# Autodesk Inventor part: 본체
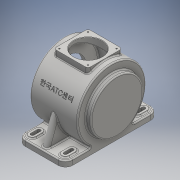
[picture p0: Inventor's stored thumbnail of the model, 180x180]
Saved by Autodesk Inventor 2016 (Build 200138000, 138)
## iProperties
Created: 2015-06
Part Number: 본체
Material: Generic
Document SubType Name: Modeling
Designer: Administrator
Density: 1 g/cm^3
Appearance: Default
Author: Administrator
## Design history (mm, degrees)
sketch "스케치1"
  geometry: C1 r 85 at (0, 0); 1 further point
  constraints: 1 centre point, 1 coincident
  dimensions: "d0" = 170 diameter of C1
extrude "돌출1" new body sketch "스케치1" stored distance "d1" = 118; taper "d3" = 0 deg; dims "d2" = 51, "d4" = 0
sketch "스케치3"
  geometry: C1 r 65 at (0, 0); 1 further point
  constraints: 1 centre point, 1 coincident
  dimensions: "d5" = 130 diameter of C1
extrude "돌출2" join sketch "스케치3" distance "d6" = 13; taper "d7" = 0 deg
sketch "스케치4"
  geometry: C1 r 65 at (0, 0); 1 further point
  constraints: 1 centre point, 1 coincident
  dimensions: "d8" = 130 diameter of C1
extrude "돌출3" join sketch "스케치4" distance "d9" = 3; taper "d10" = 0 deg
sketch "스케치7"
  geometry: L1 (71, -115)-(85, -115); L2 (85, -115)-(85, 115); L3 (85, 115)-(71, 115); L4 (71, 115)-(71, -115); 2 further points
  constraints: 8 end point, 2 parallel, 1 horizontal, 1 horizontal alignment, 1 midpoint, 1 perpendicular
  dimensions: "d16" = 14 distance of L2.end L3.end; "d17" = 230 distance of L3.end L1.start; "d18" = 85 distance from line of L2 point (0, 0)
extrude "돌출5" join sketch "스케치7" stored distance "d19" = 3; taper "d20" = 0 deg
sketch "스케치8"
  geometry: L1 (-62, 65)-(-62, -65) reference; L2 (-59, -85)-(59, -85) reference; L3 (-59, 85)-(59, 85) reference; L4 (72, 0)-(-62, 0); L5 (-51, 47.5)-(-51, 77); L6 (-51, 77)-(51, 77); L7 (51, 77)-(51, 31); L8 (51, 31)-(47.042, 29.154); L9 (47.042, 29.154)-(47.042, 23.5); L10 (47.042, 23.5)-(61.042, 23.5); L11 (61.042, 23.5)-(61.042, 15); L12 (61.042, 15)-(64.042, 15); L13 (72, -65)-(72, 65) reference; L14 (64.042, 15)-(64.042, 0); L15 (-51, 47.5)-(-62, 47.5); L16 (-62, 47.5)-(-62, 0); 1 further point
  constraints: 24 end point, 5 perpendicular, 2 midpoint, 2 point on line, 1 parallel, 1 vertical
  dimensions: "d21" = 3 distance of L11.end L12.end; "d23" = 30 diameter of L12 L4; "d24" = 14 distance of L9.end L10.end; "d25" = 47 diameter of L10 L4; "d26" = 115 deg angle of L7 L8; "d27" = 102 distance between parallel lines of L5 L7; "d28" = 62 diameter of L7.end L4; "d29" = 154 diameter of L6 L4; "d30" = 95 diameter of L15 L4; "d31" = 11 distance of L5.start L15.end; "d32" = 3.9582 distance from line of L7 L8.end
revolve "회전1" sketch "스케치8" stored, may be unused: angle "d33" = 90 deg
sketch "스케치9"
  geometry: L1 (-115, -71)-(-46.733, -71) reference; L2 (115, -85)-(-115, -85) reference; L3 (46.733, -71)-(115, -71) reference; L4 (-42.5, 88)-(42.5, 88); L5 (42.5, 88)-(42.5, 73.612); L6 (-42.5, 73.612)-(-42.5, 88); A1 r 85 centre (0, 0) between (46.733, -71) and (-46.733, -71) reference; 1 further point
  constraints: 6 end point, 2 parallel, 2 point on circle, 1 horizontal, 1 perpendicular
  dimensions: "d34" = 85 distance of L4.start L4.end; "d35" = 173 distance between parallel lines of L2 L4
extrude "돌출6" join sketch "스케치9" stored distance "d36" = 85; taper "d37" = 0 deg
sketch "스케치10"
  geometry: 2 further points
  constraints: 1 coincident
hole "구멍1" sketch "스케치10" at (42.5, 42.5) diameter "d38" = 70; stored, may be unused: countersink angle "d42" = 90 deg, drill point angle "d44" = 118 deg; dims "d39" = 6, "d40" = 4, "d41" = 2, "d43" = 8
fillet "모깎기1" dims "d45" = 7
sketch "스케치11"
  geometry: L1 (0, 78)-(71, 78); L2 (71, 78)-(71, 7); L3 (71, 7)-(0, 7); L4 (0, 7)-(0, 78); 7 further points
  constraints: 8 end point, 4 coincident, 2 midpoint, 2 parallel, 2 perpendicular, 1 horizontal, 1 horizontal alignment, 1 vertical alignment
  dimensions: "d46" = 71 distance of L1.start L1.end
hole "구멍2" sketch "스케치11" at (0, 78), (0, 7), (71, 7), (71, 78) diameter "d47" = 3.242; stored, may be unused: countersink angle "d51" = 90 deg, drill point angle "d53" = 118 deg; dims "d48" = 10, "d49" = 4, "d50" = 2, "d52" = 13
sketch "스케치12"
  geometry: A1 r 55 centre (0, 0) between (0, 55) and (55, 0); 3 further points
  constraints: 4 point on circle, 2 horizontal alignment, 2 vertical alignment, 1 centre point, 1 coincident
  dimensions: "d54" = 110 diameter of A1
hole "구멍3" sketch "스케치12" at (0, 55), (55, 0), (0, -55), (-55, 0) diameter "d55" = 3.242; stored, may be unused: countersink angle "d59" = 90 deg, drill point angle "d61" = 118 deg; dims "d56" = 8, "d57" = 4, "d58" = 2, "d60" = 11.8
sketch "스케치14"
  geometry: L1 (-115, -71)-(-46.733, -71) reference; L2 (-109, -71)-(-84.87, -4.703); L3 (-109, -71)-(-46.733, -71); A1 r 85 centre (0, 0) between (46.733, -71) and (-46.733, -71) reference; 1 further point
  constraints: 4 end point, 1 horizontal, 1 point on circle, 1 point on line
  dimensions: "d62" = 6 distance of L1.start L2.start; "d63" = 110 deg angle of L1 L2
extrude "돌출7" join sketch "스케치14" stored distance "d64" = 15; taper "d65" = 0 deg
sketch "스케치16"
  geometry: L1 (-18, 25.267)-(-18, 25.267); L2 (-9, 34.267)-(-9, 50.267); L3 (-18, 59.267)-(-18, 59.267); L4 (-27, 50.267)-(-27, 34.267); L5 (0, 68.267)-(-118, 68.267) reference; L6 (0, -161.733)-(0, 68.267) reference; L7 (0, -46.733)-(-118, -46.733); L8 (-118, 68.267)-(-118, -161.733) reference; L9 (-27, -127.733)-(-27, -143.733); L10 (-9, -143.733)-(-9, -127.733); L11 (-109, 50.267)-(-109, 34.267); L12 (-91, 34.267)-(-91, 50.267); L13 (-109, -127.733)-(-109, -143.733); L14 (-91, -143.733)-(-91, -127.733); A1 r 9 centre (-18, 50.267) between (-18, 59.267) and (-27, 50.267); A2 r 9 centre (-18, 50.267) between (-9, 50.267) and (-18, 59.267); A3 r 9 centre (-18, 34.267) between (-27, 34.267) and (-18, 25.267); A4 r 9 centre (-18, 34.267) between (-18, 25.267) and (-9, 34.267); A5 r 9 centre (-18, -143.733) between (-27, -143.733) and (-18, -152.733); A6 r 9 centre (-18, -143.733) between (-18, -152.733) and (-9, -143.733); A7 r 9 centre (-18, -127.733) between (-9, -127.733) and (-18, -118.733); A8 r 9 centre (-18, -127.733) between (-18, -118.733) and (-27, -127.733); A9 r 9 centre (-100, 34.267) between (-109, 34.267) and (-100, 25.267); A10 r 9 centre (-100, 34.267) between (-100, 25.267) and (-91, 34.267); A11 r 9 centre (-100, 50.267) between (-91, 50.267) and (-100, 59.267); A12 r 9 centre (-100, 50.267) between (-100, 59.267) and (-109, 50.267); A13 r 9 centre (-100, -143.733) between (-109, -143.733) and (-100, -152.733); A14 r 9 centre (-100, -143.733) between (-100, -152.733) and (-91, -143.733); A15 r 9 centre (-100, -127.733) between (-91, -127.733) and (-100, -118.733); A16 r 9 centre (-100, -127.733) between (-100, -118.733) and (-109, -127.733); 13 further points
  constraints: 32 point on circle, 22 end point, 16 centre point, 15 point on line, 8 tangent, 3 equal radius, 2 horizontal, 2 midpoint, 2 parallel, 1 perpendicular, 1 vertical, 63 other
  dimensions: "d67" = 18 distance of point (-9, 59.267) point (-27, 59.267); "d68" = 9 radius of A1; "d69" = 16 distance of A1.centre A3.centre; "d70" = 18 distance from line of A1.centre L6; "d71" = 194 diameter of A1.centre L7; "d74" = 178 distance of L4.start L9.start; "d77" = 82 distance of L4.start L11.start
extrude "돌출8" join sketch "스케치16" distance "d80" = 3; taper "d81" = 0 deg
sketch "스케치17"
  geometry: L1 (-22, 34.267)-(-22, 50.267); L2 (-14, 34.267)-(-14, 50.267); A1 r 9 centre (-18, 34.267) between (-27, 34.267) and (-9, 34.267) reference; A2 r 9 centre (-18, 50.267) between (-9, 50.267) and (-27, 50.267) reference; A3 r 4 centre (-18, 34.267) between (-22, 34.267) and (-14, 34.267); A4 r 4 centre (-18, 50.267) between (-14, 50.267) and (-22, 50.267); 1 further point
  constraints: 4 end point, 4 point on circle, 2 centre point, 2 coincident, 2 horizontal alignment, 2 tangent
  dimensions: "d88" = 8 diameter of A3; "d89" = 8 diameter of A4
extrude "돌출9" cut sketch "스케치17" stored distance "d90" = 3; taper "d91" = 0 deg
fillet "모깎기2" dims "d98" = 18
fillet "모깎기3" dims "d99" = 7.5
fillet "모깎기4" dims "d100" = 3
fillet "모깎기5" dims "d101" = 3
fillet "모깎기6" dims "d102" = 3
fillet "모깎기7" dims "d103" = 3
fillet "모깎기8" dims "d104" = 3
node "작업 평면1"
sketch "스케치19"
  geometry: 3 further points
  constraints: 1 coincident, 1 other
extrude "돌출10" join sketch "스케치19" distance "d106" = 0.5; taper "d107" = 0 deg
chamfer "모따기1" distance "d108" = 1; stored, may be unused: second distance "d109" = 2, angle "d110" = 45 deg
fillet "모깎기9" dims "d111" = 3, "d112" = 0.3
fillet "모깎기10" dims "d113" = 3
node "솔리드1"
mirror "대칭1"
pattern_linear "직사각형 패턴2" dims "d94" = 178, "d97" = 82
